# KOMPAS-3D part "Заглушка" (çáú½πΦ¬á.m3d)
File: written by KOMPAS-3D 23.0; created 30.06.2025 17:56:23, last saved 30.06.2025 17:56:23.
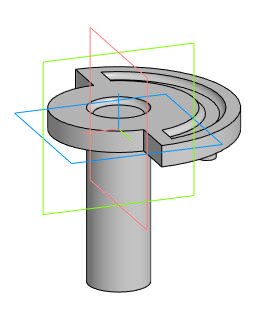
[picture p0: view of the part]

Document properties: Автор: Inspektor_Kot; Полное имя файла: I:\Autodesk Inventor Projects\2025 Варианты\Демовариант\Заглушка.m3d

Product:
- Part/product: Заглушка

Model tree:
1. Операция без истории:1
